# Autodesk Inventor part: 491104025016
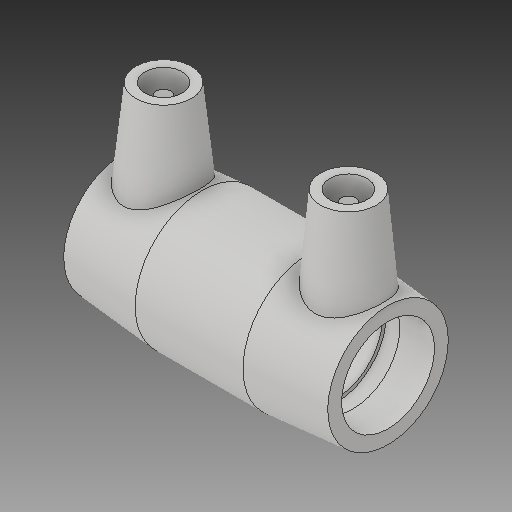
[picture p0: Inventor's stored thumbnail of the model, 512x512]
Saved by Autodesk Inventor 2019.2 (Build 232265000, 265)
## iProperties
Created: 2017-06
Part Number: 491104025016
Material: Generic
Description: PLASSON REDUCING COUPLER 25-16
Document SubType Name: Modeling
Designer: KIM
Mass: 54.8237 g
Surface Area: 155.252 cm^2
Volume: 54.8237 cm^3
Density: 1 g/cm^3
Appearance: Default
Author: KIM
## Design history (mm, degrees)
derived "491104.ipt"
feature "Solid1::491104.ipt"
tag "TaggingFeature1"
body "Solid1"
other parameters: "d0" = 71, "d2" = 36, "d3" = 35, "d4" = 21, "d5" = 32.4, "d7" = 16, "d8" = 168 deg, "d10" = 14, "d11" = 4.66667, "d13" = 71, "d14" = 17.6296, "d15" = 35, "d18" = 16, "d19" = 1.75, "d20" = 168 deg, "d22" = 108.92847, "d25" = 135 deg, "d29" = 38, "d30" = 15, "d31" = 24.85, "d34" = 6 deg, "d35" = 15, "d38" = 29.2, "d39" = 5 deg, "d41" = 4, "d42" = 14, "d43" = 0, "d45" = 4, "d46" = 14, "d47" = 0, "d48" = 36, "d49" = 25, "d50" = 36, "d52" = 14.4, "d53" = 14, "d54" = 4.66667, "d55" = 168 deg, "d56" = 21, "d57" = 35, "d58" = 32.4, "d59" = 1.75, "d60" = 135 deg, "d61" = 38, "d62" = 15, "d64" = 4, "d66" = 5 deg, "d67" = 14, "d68" = 0, "d69" = 24.85, "d70" = 36, "d71" = 36, "d73" = 33.84, "d76" = 1.75, "d77" = 168 deg, "d78" = 25, "d79" = 1.75, "d80" = 35, "d81" = 14.4, "d82" = 33.84, "d83" = 120 deg, "d88" = 15, "d89" = 24.25, "d90" = 5 deg, "d92" = 4, "d93" = 14, "d94" = 0, "d95" = 3, "d96" = 0, "d97" = 3, "d98" = 0, "d99" = 10.15, "d100" = 2.5375, "d101" = 32.8248, "d102" = 20 deg, "d103" = 10.15, "d104" = 2.5375, "d105" = 32.8248, "d106" = 3.60705, "d107" = 3, "d108" = 0, "d109" = 3, "d110" = 0, "d_1" = 16, "L_" = 71, "L_2" = 35, "D_1" = 36, "A_1" = 38, "d_2" = 12, "L_1" = 35, "d_" = 25, "A_" = 38, "D_" = 36
